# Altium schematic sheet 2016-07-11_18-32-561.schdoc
size 186 x 111 mm; SheetNumber: 1; SheetTotal: 1
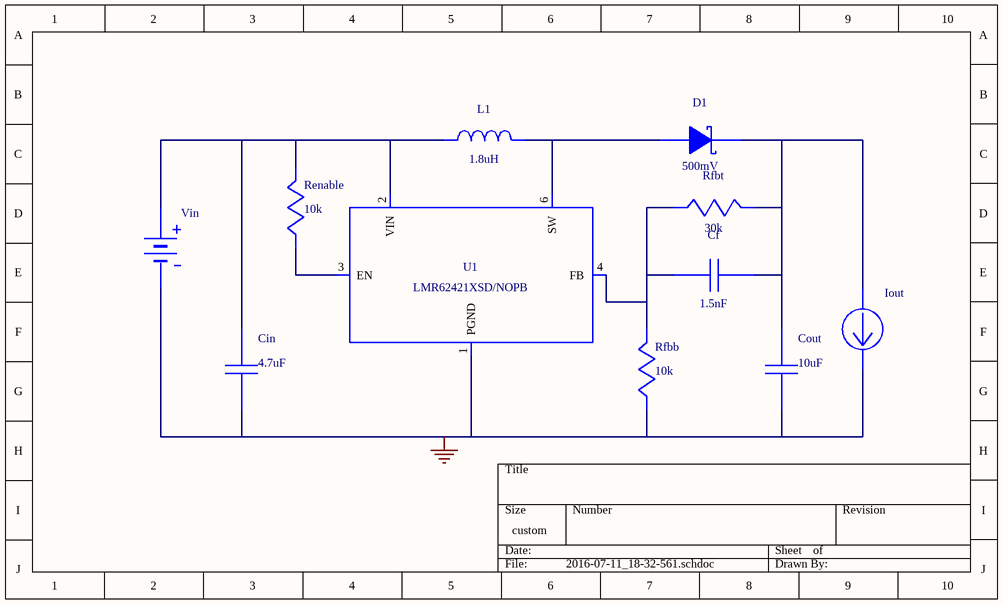
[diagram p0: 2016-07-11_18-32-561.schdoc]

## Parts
Cf  value 1.5nF  (hidden comment: CC0805KRX7R9BB152)
Cin  value 4.7uF  (hidden comment: GRM188R60J475KE19D)
Cout  value 10uF  (hidden comment: GRM188R60J106ME47D)
D1  value 500mV  (hidden comment: B220-13-F)
Iout  WB_CURRENT_LOAD  (value not drawn)
L1  value 1.8uH  (hidden comment: SDR0403-1R8ML)
Renable  value 10k  (hidden comment: CRCW040210K0FKED)
Rfbb  value 10k  (hidden comment: CRCW040210K0FKED)
Rfbt  value 30k  (hidden comment: RC0603FR-0730KL)
U1  LMR62421XSD/NOPB
Vin  WB_BATTERY  (value not drawn)

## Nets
0: Cin.2 Cout.2 Iout.2(-) Rfbb.2 U1.1(PGND) U1.5(AGND) U1.7(DAP) Vin.2(-)
NetCf_1: Cf.1 Cout.1 D1.1(K) Iout.1(+) Rfbt.1
NetCf_2: Cf.2 Rfbb.1 Rfbt.2 U1.4(FB)
NetCin_1: Cin.1 L1.1 Renable.1 U1.2(VIN) Vin.1(+)
NetD1_2: D1.2(A) L1.2 U1.6(SW)
NetRenable_2: Renable.2 U1.3(EN)

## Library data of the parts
Cf = CC0805KRX7R9BB152: CC0805KRX7R9BB15; Manufacturer Name: Yageo America
Cin = GRM188R60J475KE19D: GRM188R60J475KE1; Manufacturer Name: MuRata
Cout = GRM188R60J106ME47D: GRM188R60J106ME4; Manufacturer Name: MuRata
D1 = B220-13-F: Manufacturer Name: Diodes Inc.
L1 = SDR0403-1R8ML: Manufacturer Name: Bourns
Renable Rfbb = CRCW040210K0FKED: Manufacturer Name: Vishay-Dale
Rfbt = RC0603FR-0730KL: Manufacturer Name: Yageo America
U1 = LMR62421XSD/NOPB: Manufacturer Name: Texas Instruments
